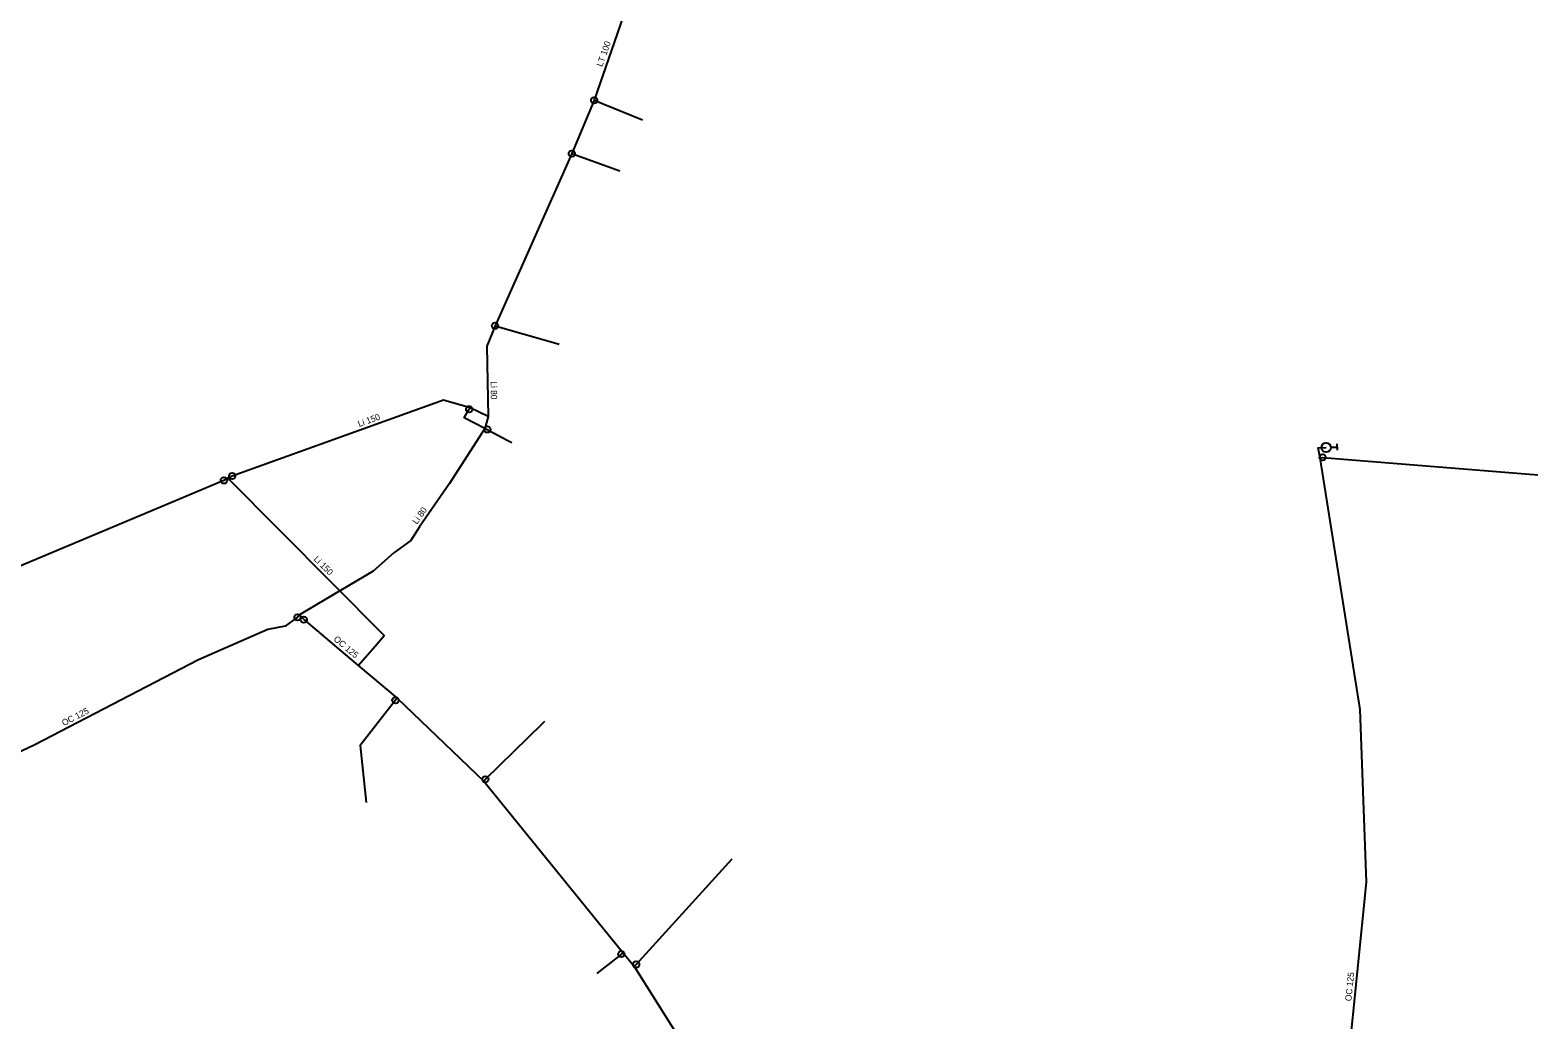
# Model space of a CAD drawing. Extents: x -684724 to -684366, y -1163865 to -1163489.
# Drawn here: x -684495.3 to -684375.2, y -1163792.2 to -1163713.4 of the extents above; entities that cross this region are included whole.
import ezdxf

# ---------------------------------------------------------------- set-up
doc = ezdxf.new("R2010")
doc.units = 0
for name, color, linetype in [('Hydranty', 7, 'Continuous'), ('Popis vodovodních řadů', 7, 'Continuous'), ('Vod přípojky-voda pitná', 7, 'Continuous'), ('Vodovodní řad', 7, 'Continuous'), ('Vodovodní šoupata', 7, 'Continuous')]:
    doc.layers.add(name, color=color, linetype=linetype)

msp = doc.modelspace()

# ---------------------------------------------------------------- linework, layer by layer
at = {"layer": 'Hydranty'}
for p, q in [((-684391.71, -1163746.62), (-684391.21, -1163746.6)), ((-684391.22, -1163746.35), (-684391.19, -1163746.85))]:
    msp.add_line(p, q, dxfattribs=at)
msp.add_circle((-684392.08, -1163746.64), 0.375, dxfattribs=at)
at = {"layer": 'Vod přípojky-voda pitná'}
for points in [[(-684450.35, -1163719), (-684446.5, -1163720.57)], [(-684452.13, -1163723.25), (-684448.32, -1163724.63)], [(-684458.24, -1163736.95), (-684453.15, -1163738.4)], [(-684459.05, -1163745.12), (-684460.69, -1163744.27), (-684460.3, -1163743.59), (-684460.23, -1163743.48)], [(-684459.05, -1163745.12), (-684458.86, -1163745.2), (-684457.22, -1163746.07), (-684456.91, -1163746.25)], [(-684392.55, -1163747.46), (-684392.35, -1163747.42), (-684375.22, -1163748.82)], [(-684466.03, -1163766.59), (-684466.17, -1163766.75), (-684468.97, -1163770.35), (-684468.49, -1163774.88)], [(-684459.14, -1163773.18), (-684459.01, -1163773.04), (-684454.46, -1163768.61), (-684454.28, -1163768.42)], [(-684447.19, -1163787.9), (-684447.01, -1163787.78), (-684439.36, -1163779.38)], [(-684448.07, -1163786.84), (-684448.18, -1163786.95), (-684449.99, -1163788.37), (-684450.15, -1163788.51)]]:
    msp.add_lwpolyline(points, dxfattribs=at)
at = {"layer": 'Vodovodní řad'}
for points in [[(-684441.59, -1163693.72), (-684450.35, -1163719), (-684452.13, -1163723.25), (-684458.24, -1163736.95), (-684458.9, -1163738.57)], [(-684458.9, -1163738.57), (-684458.8, -1163744.18)], [(-684458.8, -1163744.18), (-684460.23, -1163743.48), (-684462.35, -1163742.86), (-684479.17, -1163748.91)], [(-684458.8, -1163744.18), (-684459.05, -1163745.12), (-684461.86, -1163749.51), (-684464.26, -1163752.94), (-684464.96, -1163754.05), (-684466.29, -1163755.01), (-684467.95, -1163756.48), (-684472.42, -1163759.13)], [(-684408.88, -1163829.66), (-684409.14, -1163829.21), (-684398.24, -1163818.34), (-684394.87, -1163812.64), (-684392.17, -1163803.88), (-684390.3, -1163795.45), (-684388.86, -1163781.22), (-684389.37, -1163767.49), (-684392.55, -1163747.46), (-684392.72, -1163746.65), (-684392.08, -1163746.64)], [(-684479.83, -1163749.26), (-684483.88, -1163750.96)], [(-684479.51, -1163749.08), (-684479.83, -1163749.26)], [(-684479.17, -1163748.91), (-684479.51, -1163749.08)], [(-684467.79, -1163762.44), (-684467.06, -1163761.6), (-684479.51, -1163749.08)], [(-684483.88, -1163750.96), (-684518.01, -1163765.28)], [(-684472.42, -1163759.13), (-684473.81, -1163759.96)], [(-684473.97, -1163760.15), (-684474.96, -1163760.85), (-684476.34, -1163761.11), (-684481.86, -1163763.54), (-684494.87, -1163770.29), (-684511.01, -1163777.95)], [(-684473.81, -1163759.96), (-684473.97, -1163760.15)], [(-684473.47, -1163760.33), (-684473.81, -1163759.96)], [(-684473.47, -1163760.33), (-684469.13, -1163763.98)], [(-684469.13, -1163763.98), (-684467.79, -1163762.44)], [(-684469.13, -1163763.98), (-684466.03, -1163766.59), (-684459.14, -1163773.18), (-684448.07, -1163786.84), (-684447.19, -1163787.9), (-684440.2, -1163798.98), (-684434.04, -1163809.69), (-684429.82, -1163815.12), (-684418.5, -1163829.64), (-684416.68, -1163831.53), (-684413.31, -1163835.17), (-684410.42, -1163832.17)]]:
    msp.add_lwpolyline(points, dxfattribs=at)
at = {"layer": 'Vodovodní šoupata'}
for centre in [(-684450.35, -1163719), (-684452.13, -1163723.25), (-684458.24, -1163736.95), (-684460.3, -1163743.59), (-684458.86, -1163745.2), (-684392.35, -1163747.42), (-684479.83, -1163749.26), (-684479.17, -1163748.91), (-684473.97, -1163760.15), (-684473.47, -1163760.33), (-684466.17, -1163766.75), (-684459.01, -1163773.04), (-684448.18, -1163786.95), (-684447.01, -1163787.78)]:
    msp.add_circle(centre, 0.25, dxfattribs=at)

# ---------------------------------------------------------------- texts
at = {"layer": 'Popis vodovodních řadů'}
for s, rotation, p in [('LT 100', 70.8878, (-684449.7, -1163716.37)), ('Li 80', 271.0212, (-684458.6, -1163741.37)), ('Li 150', 19.7832, (-684469.06, -1163745.01)), ('Li 80', 55.0192, (-684464.46, -1163752.79)), ('Li 150', 314.8394, (-684472.72, -1163755.56)), ('OC 125', 319.9357, (-684471.14, -1163761.96)), ('OC 125', 27.4217, (-684492.57, -1163768.82)), ('OC 125', 84.2216, (-684390.07, -1163790.72))]:
    msp.add_text(s, height=0.5, rotation=rotation, dxfattribs=at).set_placement(p)

doc.saveas('drawing.dxf')
